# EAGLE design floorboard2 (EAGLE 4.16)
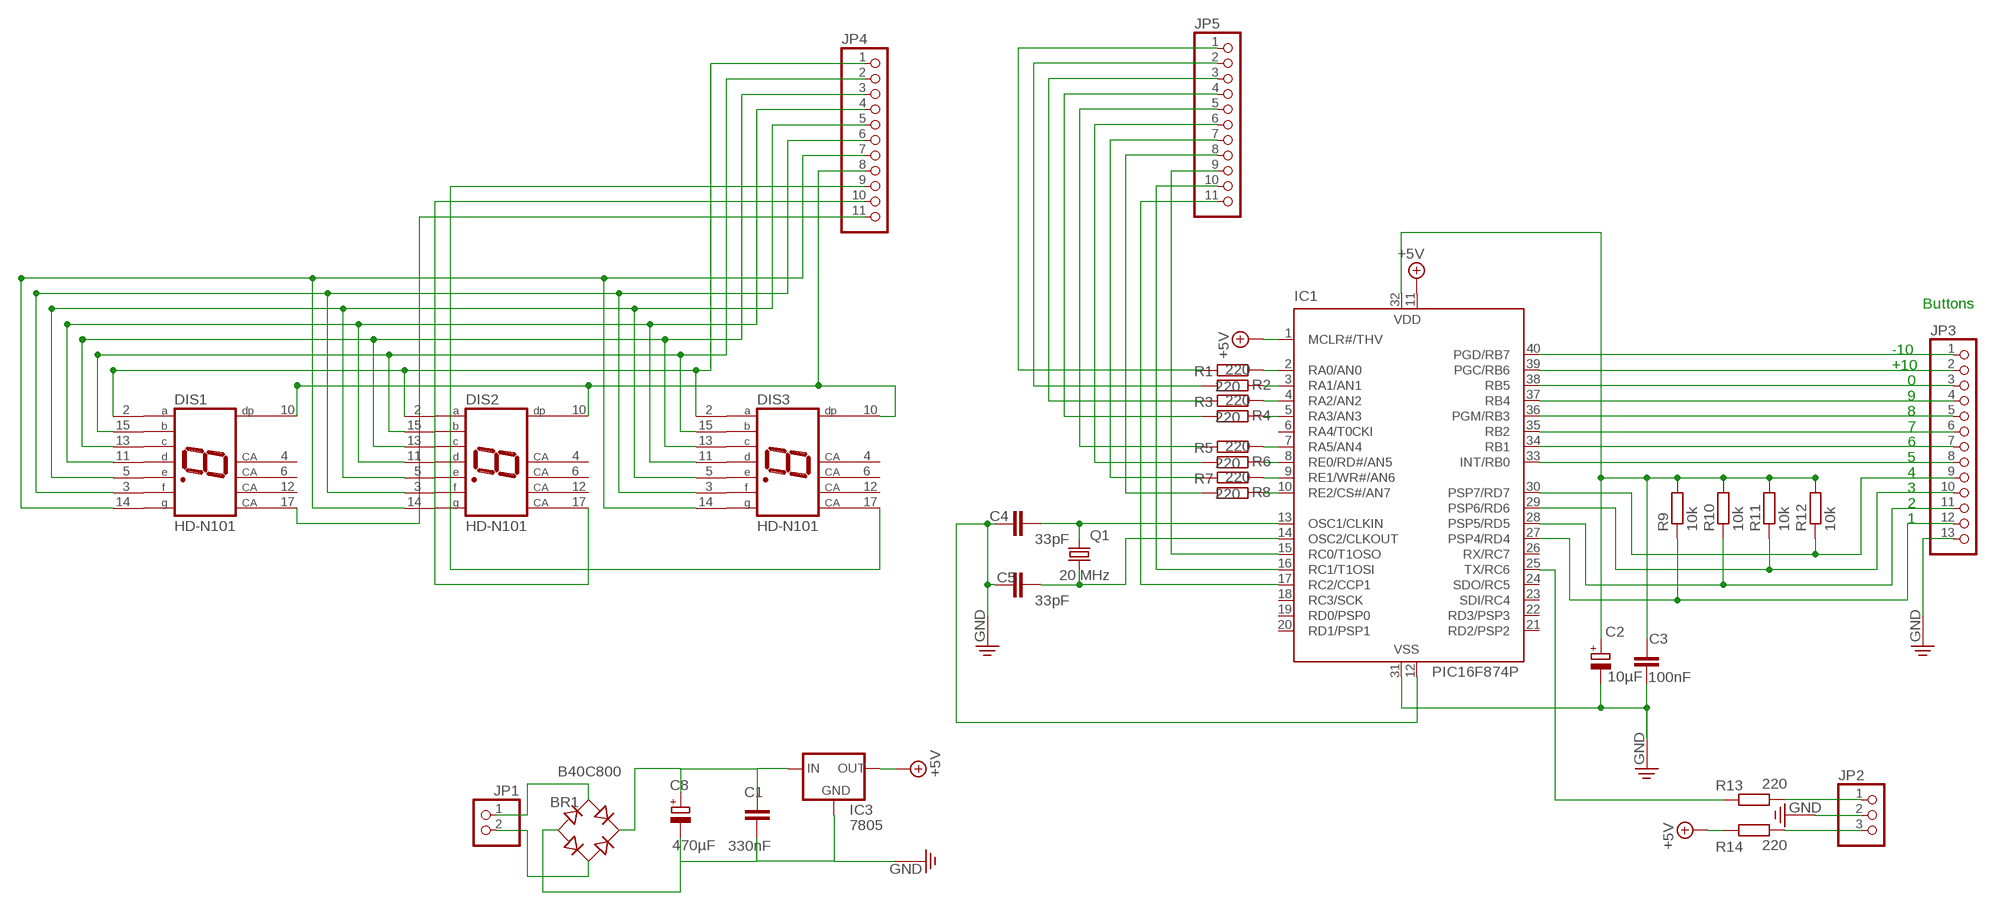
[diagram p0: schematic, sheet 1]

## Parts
BR1  B40C800  RB1A  [RB1A]
C1  330nF  C-EU025-025X050  [C025-025X050]
C2  10µF  CPOL-EUE2-5  [E2-5]
C3  100nF  C-EU025-025X050  [C025-025X050]
C4  33pF  C-EU025-025X050  [C025-025X050]
C5  33pF  C-EU025-025X050  [C025-025X050]
C8  470µF  CPOL-EUE2-5  [E2-5]
DIS1  HD-N101  [HDSP-Q]
DIS2  HD-N101  [HDSP-Q]
DIS3  HD-N101  [HDSP-Q]
IC1  PIC16F874P  [DIL40]
IC3  7805  78XXS  [78XXS]
JP1  PINHD-1X2  [1X02]
JP2  PINHD-1X3  [1X03]
JP3  PINHD-1X13  [1X13]
JP4  PINHD-1X11  [1X11]
JP5  PINHD-1X11  [1X11]
Q1  20 MHz  CRYTALHC18U-V  [HC18U-V]
R1  220  R-EU_0207/10  [0207/10]
R2  220  R-EU_0207/10  [0207/10]
R3  220  R-EU_0207/10  [0207/10]
R4  220  R-EU_0207/2V  [0207/2V]
R5  220  R-EU_0207/2V  [0207/2V]
R6  220  R-EU_0207/2V  [0207/2V]
R7  220  R-EU_0207/2V  [0207/2V]
R8  220  R-EU_0207/2V  [0207/2V]
R9  10k  R-EU_0207/10  [0207/10]
R10  10k  R-EU_0207/10  [0207/10]
R11  10k  R-EU_0207/10  [0207/10]
R12  10k  R-EU_0207/10  [0207/10]
R13  220  R-EU_0207/2V  [0207/2V]
R14  220  R-EU_0207/2V  [0207/2V]

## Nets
+5V: IC1.1(MCLR#/THV) IC1.11(VDD) IC3.OUT R14.1
+-9V: BR1.+ C1.1 C8.+ IC3.IN
GND: BR1.- C1.2 C2.- C3.2 C4.1 C5.1 C8.- IC1.12(VSS) IC1.31(VSS) IC3.GND JP2.2 JP3.13
N$1: BR1.AC1 JP1.1
N$2: BR1.AC2 JP1.2
N$4: IC1.2(RA0/AN0) R1.2
N$5: IC1.3(RA1/AN1) R2.1
N$6: IC1.4(RA2/AN2) R3.2
N$7: IC1.5(RA3/AN3) R4.1
N$8: IC1.7(RA5/AN4) R5.2
N$9: IC1.8(RE0/RD#/AN5) R6.1
N$10: IC1.9(RE1/WR#/AN6) R7.2
N$11: IC1.10(RE2/CS#/AN7) R8.1
N$12: IC1.40(PGD/RB7) JP3.1
N$13: IC1.39(PGC/RB6) JP3.2
N$14: IC1.38(RB5) JP3.3
N$15: IC1.37(RB4) JP3.4
N$16: IC1.36(PGM/RB3) JP3.5
N$17: IC1.35(RB2) JP3.6
N$18: IC1.34(RB1) JP3.7
N$19: IC1.33(INT/RB0) JP3.8
N$20: C2.+ C3.1 IC1.32(VDD) R9.2 R10.2 R11.2 R12.2
N$21: IC1.30(PSP7/RD7) JP3.9 R12.1
N$22: IC1.29(PSP6/RD6) JP3.10 R11.1
N$23: IC1.28(PSP5/RD5) JP3.11 R10.1
N$24: IC1.27(PSP4/RD4) JP3.12 R9.1
N$25: IC1.25(TX/RC6) R13.1
N$26: JP2.1 R13.2
N$27: JP2.3 R14.2
N$28: C4.2 IC1.13(OSC1/CLKIN) Q1.2
N$29: C5.2 IC1.14(OSC2/CLKOUT) Q1.1
N$30: DIS1.2(A) DIS2.2(A) DIS3.2(A) JP4.1
N$31: DIS1.15(B) DIS2.15(B) DIS3.15(B) JP4.2
N$32: DIS2.17(CA) JP4.10
N$33: DIS1.17(CA) JP4.11
N$37: JP5.7 R7.1
N$38: DIS1.13(C) DIS2.13(C) DIS3.13(C) JP4.3
N$39: DIS1.11(D) DIS2.11(D) DIS3.11(D) JP4.4
N$40: JP5.6 R6.2
N$41: DIS1.3(F) DIS2.3(F) DIS3.3(F) JP4.6
N$42: JP5.5 R5.1
N$43: JP5.4 R4.2
N$44: JP5.3 R3.1
N$45: JP5.2 R2.2
N$46: DIS1.5(E) DIS2.5(E) DIS3.5(E) JP4.5
N$47: JP5.1 R1.1
N$48: DIS1.14(G) DIS2.14(G) DIS3.14(G) JP4.7
N$49: JP5.8 R8.2
N$50: IC1.15(RC0/T1OSO) JP5.9
N$51: DIS1.10(DP) DIS2.10(DP) DIS3.10(DP) JP4.8
N$52: DIS3.17(CA) JP4.9
N$53: IC1.16(RC1/T1OSI) JP5.10
N$54: IC1.17(RC2/CCP1) JP5.11
Unconnected: DIS1.4(CA) DIS1.6(CA) DIS1.12(CA) DIS2.4(CA) DIS2.6(CA) DIS2.12(CA) DIS3.4(CA) DIS3.6(CA) DIS3.12(CA) IC1.6(RA4/T0CKI) IC1.18(RC3/SCK) IC1.19(RD0/PSP0) IC1.20(RD1/PSP1) IC1.21(RD2/PSP2) IC1.22(RD3/PSP3) IC1.23(SDI/RC4) IC1.24(SDO/RC5) IC1.26(RX/RC7)

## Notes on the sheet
- Buttons
- -10
- +10
- 0
- 9
- 8
- 7
- 6
- 5
- 4
- 3
- 2
- 1

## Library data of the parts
BR1 = rectifier:RB1A: RECTIFIER 1 A
C1 C3-C5 = rcl:C-EU: CAPACITOR, European symbol
C2 C8 = rcl:CPOL-EU: POLARIZED CAPACITOR, European symbol
DIS1-DIS3 = display-hp:HD-N101: LED DISPLAY 1-character 7 segment, decimal point right
IC1 = microchip:PIC16F87*: MICROCONTROLLER
IC3 = v-reg:78XXS: VOLTAGE REGULATOR
JP1 = pinhead:PINHD-1X2: PIN HEADER
JP2 = pinhead:PINHD-1X3: PIN HEADER
JP3 = pinhead:PINHD-1X13: PIN HEADER
JP4 JP5 = pinhead:PINHD-1X11: PIN HEADER
Q1 = crystal:CRYTAL: CRYSTAL
R1-R14 = rcl:R-EU_: RESISTOR, European symbol

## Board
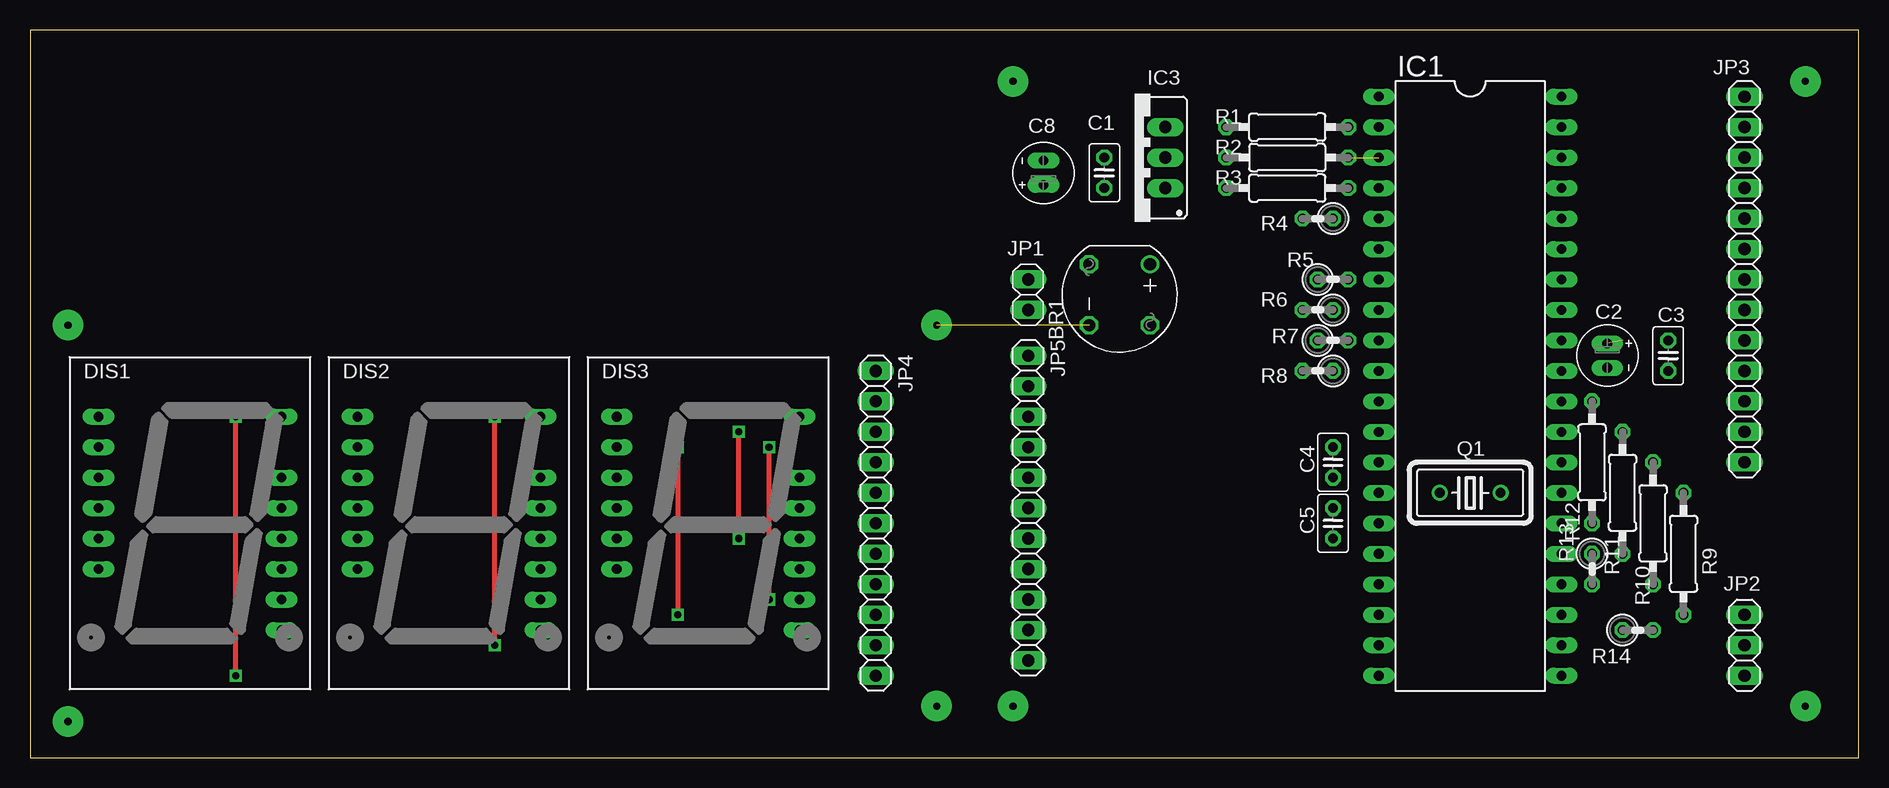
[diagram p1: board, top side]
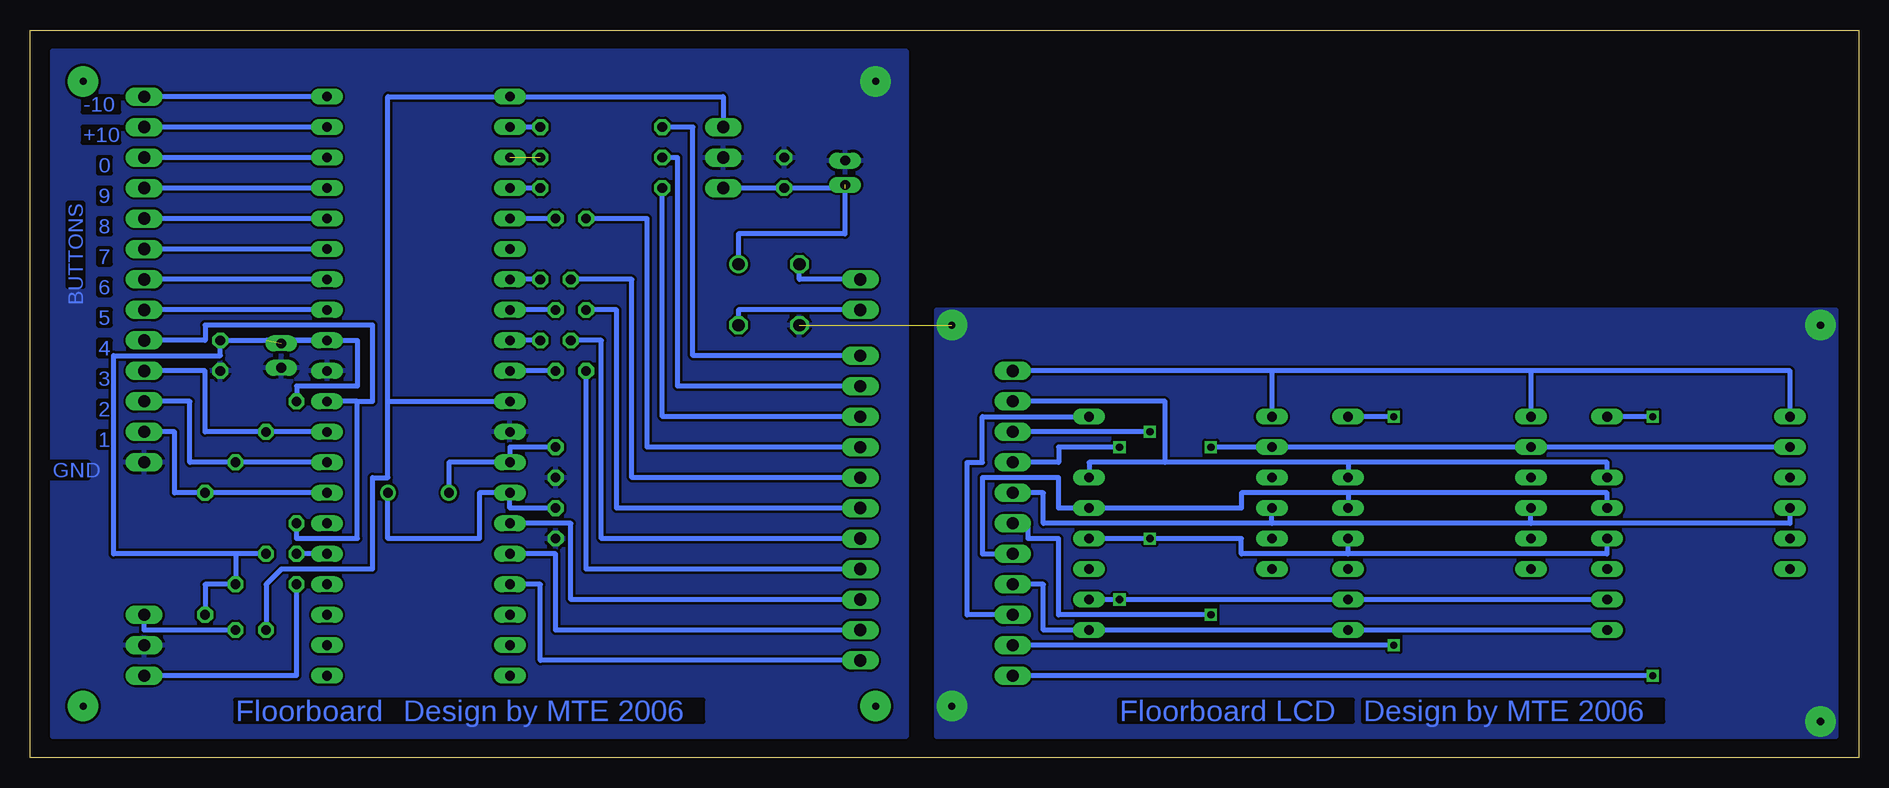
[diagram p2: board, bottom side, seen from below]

Size 152.38 x 60.63 mm. Coordinates in mm from the lower left corner, seen from the top.
Outline: 0,0 152.38,0 152.38,60.63 0,60.63 0,0
Copper layers (1*16): Top 0.035mm / dielectric 1.5mm / Bottom 0.035mm
Design rules "default": minimum track width 10mil, minimum drill 24mil, track to track 8mil, track to pad 8mil, pad to pad 8mil, via to via 8mil, smd to smd 8mil, copper to edge 40mil, drill to drill 8mil, minimum pad ring 10mil, minimum via ring 8mil, stop-mask expansion 4mil, vias tented up to drill 0mil, thermal gap 10mil

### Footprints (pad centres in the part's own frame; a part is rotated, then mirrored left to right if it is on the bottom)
RB1A = drill 1.016 round: + -2.54,2.54 | drill 1.016 octagon: - 2.54,-2.54; AC1 2.54,2.54; AC2 -2.54,-2.54
C025-025X050 = drill 0.813 octagon: 1 -1.27,0; 2 1.27,0
E2-5 = drill 0.813 pad 1.27 long: + -1.016,0; - 1.016,0
HDSP-Q = drill 0.813 long: 2 -7.62,8.89; 3 -7.62,6.35; 4 -7.62,3.81; 5 -7.62,1.27; 6 -7.62,-1.27; 7 -7.62,-3.81; 10 7.62,-8.89; 11 7.62,-6.35; 12 7.62,-3.81; 13 7.62,-1.27; 14 7.62,1.27; 15 7.62,3.81; 17 7.62,8.89
DIL40 = drill 0.813 long: 1 -24.13,-7.62; 2 -21.59,-7.62; 3 -19.05,-7.62; 4 -16.51,-7.62; 5 -13.97,-7.62; 6 -11.43,-7.62; 7 -8.89,-7.62; 8 -6.35,-7.62; 9 -3.81,-7.62; 10 -1.27,-7.62; 11 1.27,-7.62; 12 3.81,-7.62; 13 6.35,-7.62; 14 8.89,-7.62; 15 11.43,-7.62; 16 13.97,-7.62; 17 16.51,-7.62; 18 19.05,-7.62; 19 21.59,-7.62; 20 24.13,-7.62; 21 24.13,7.62; 22 21.59,7.62; 23 19.05,7.62; 24 16.51,7.62; 25 13.97,7.62; 26 11.43,7.62; 27 8.89,7.62; 28 6.35,7.62; 29 3.81,7.62; 30 1.27,7.62; 31 -1.27,7.62; 32 -3.81,7.62; 33 -6.35,7.62; 34 -8.89,7.62; 35 -11.43,7.62; 36 -13.97,7.62; 37 -16.51,7.62; 38 -19.05,7.62; 39 -21.59,7.62; 40 -24.13,7.62
78XXS = drill 1.016 long: GND 0,-2.54; IN -2.54,-2.54; OUT 2.54,-2.54
1X02 = drill 1.016 long: 1 -1.27,0; 2 1.27,0
1X03 = drill 1.016 long: 1 -2.54,0; 2 0,0; 3 2.54,0
1X13 = drill 1.016 long: 1 -15.24,0; 2 -12.7,0; 3 -10.16,0; 4 -7.62,0; 5 -5.08,0; 6 -2.54,0; 7 0,0; 8 2.54,0; 9 5.08,0; 10 7.62,0; 11 10.16,0; 12 12.7,0; 13 15.24,0
1X11 = drill 1.016 long: 1 -12.7,0; 2 -10.16,0; 3 -7.62,0; 4 -5.08,0; 5 -2.54,0; 6 0,0; 7 2.54,0; 8 5.08,0; 9 7.62,0; 10 10.16,0; 11 12.7,0
HC18U-V = drill 0.813 round: 1 -2.54,0; 2 2.54,0
0207/10 = drill 0.813 octagon: 1 -5.08,0; 2 5.08,0
0207/2V = drill 0.813 octagon: 1 -1.27,0; 2 1.27,0

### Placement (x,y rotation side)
BR1  90.8,38.57 270 top
C1  89.53,48.73 90 top
C2  131.44,33.49 270 top
C3  136.52,33.49 270 top
C4  108.58,24.6 90 top
C5  108.58,19.52 90 top
C8  84.45,48.73 90 top
DIS1  13.33,19.52 0 top
DIS2  34.92,19.52 0 top
DIS3  56.51,19.52 0 top
IC1  120.01,30.95 270 top
IC3  92.07,50 90 top
JP1  83.18,38.57 90 top
JP2  142.87,9.36 90 top
JP3  142.87,39.84 270 top
JP4  70.48,19.52 270 top
JP5  83.18,20.79 270 top
Q1  120.01,22.06 180 top
R1  104.77,52.54 0 top
R2  104.77,50 180 top
R3  104.77,47.46 0 top
R4  107.31,44.92 180 top
R5  108.58,39.84 0 top
R6  107.31,37.3 180 top
R7  108.58,34.76 0 top
R8  107.31,32.22 180 top
R9  137.79,16.98 270 top
R10  135.25,19.52 270 top
R11  132.71,22.06 270 top
R12  130.17,24.6 90 top
R13  130.17,15.71 270 top
R14  133.98,10.63 0 top

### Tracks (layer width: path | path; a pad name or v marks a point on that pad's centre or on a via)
+5V
  Bottom 0.406: IC3.OUT 94.61,55.08 IC1.1 122.55,55.08 122.55,29.68 | 122.55,29.68 IC1.11 | R14.1 132.71,14.44 131.44,15.71 123.82,15.71 123.82,23.33 122.55,23.33 122.55,29.68
+-9V  (1 unrouted)
  Bottom 0.406: 84.45,47.46 C1.1 | BR1.+ 93.34,43.65 84.45,43.65 84.45,47.46 | 84.45,47.46 IC3.IN
GND  (via drill 0.6 pad 2.54)  (1 unrouted)
  other vias: 81.91,56.35 75.56,36.03 75.56,4.28 3.17,3.01 3.17,36.03
  pour Bottom: 150.49,58.89 79.37,58.89 79.37,1.74 150.49,1.74
  pour Bottom: 1.9,37.3 1.9,1.74 76.83,1.74 76.83,37.3
N$1
  Bottom 0.406: BR1.AC1 93.34,37.3 JP1.1
N$2
  Bottom 0.406: JP1.2 88.26,39.84 BR1.AC2
N$3  (via drill 0.6 pad 2.54)
  other vias: 147.95,56.35
N$4
  Bottom 0.406: R1.2 IC1.2
N$5  (1 unrouted)
N$6
  Bottom 0.406: R3.2 IC1.4
N$7
  Bottom 0.406: R4.1 IC1.5
N$8
  Bottom 0.406: R5.2 IC1.7
N$9
  Bottom 0.406: R6.1 IC1.8
N$10
  Bottom 0.406: R7.2 IC1.9
N$11
  Bottom 0.406: R8.1 IC1.10
N$12
  Bottom 0.406: IC1.40 JP3.1
N$13
  Bottom 0.406: IC1.39 JP3.2
N$14
  Bottom 0.406: IC1.38 JP3.3
N$15
  Bottom 0.406: IC1.37 JP3.4
N$16
  Bottom 0.406: IC1.36 JP3.5
N$17
  Bottom 0.406: IC1.35 JP3.6
N$18
  Bottom 0.406: IC1.34 JP3.7
N$19
  Bottom 0.406: IC1.33 JP3.8
N$20  (1 unrouted)
  Bottom 0.406: IC1.32 132.71,34.76 IC1.32 | IC1.32 C3.1 136.52,33.49 145.41,33.49 145.41,16.98 135.25,16.98 | R12.2 130.17,30.95 125.09,30.95 125.09,34.76 IC1.32 | R11.2 135.25,16.98 | 135.25,16.98 R10.2 137.79,14.44 R9.2
N$21
  Bottom 0.406: 125.09,29.68 IC1.30 | 125.09,29.68 125.09,18.25 130.17,18.25 R12.1 | 125.09,29.68 123.82,29.68 123.82,36.03 137.79,36.03 137.79,34.76 JP3.9
N$22
  Bottom 0.406: IC1.29 R11.1 137.79,27.14 137.79,32.22 JP3.10
N$23
  Bottom 0.406: IC1.28 R10.1 139.06,24.6 139.06,29.68 JP3.11
N$24
  Bottom 0.406: IC1.27 R9.1 140.33,22.06 140.33,27.14 JP3.12
N$25
  Bottom 0.406: IC1.25 R13.1
N$26
  Bottom 0.406: R13.2 130.17,6.82 JP2.1
N$27
  Bottom 0.406: R14.2 142.87,10.63 JP2.3
N$28
  Bottom 0.406: C4.2 112.39,25.87 IC1.13 117.47,24.6 Q1.2
N$29
  Bottom 0.406: C5.2 112.39,20.79 IC1.14 114.93,22.06 114.93,18.25 122.55,18.25 Q1.1
N$30
  Bottom 0.406: DIS1.2 5.71,32.22 27.3,32.22 | 27.3,32.22 DIS2.2 | 27.3,32.22 48.89,32.22 | 48.89,32.22 DIS3.2 | 48.89,32.22 JP4.1
N$31
  Bottom 0.406: DIS1.15 20.95,24.6 42.54,24.6 | 42.54,24.6 DIS2.15 | 42.54,24.6 57.78,24.6 | 57.78,24.6 64.13,24.6 DIS3.15 | JP4.2 57.78,29.68 57.78,24.6
N$32  (via drill 0.6)
  Top 0.406: v38.73,9.36 v38.73,28.41
  Bottom 0.406: v38.73,9.36 JP4.10 | v38.73,28.41 DIS2.17
N$33  (via drill 0.6)
  Top 0.406: v17.14,6.82 v17.14,28.41
  Bottom 0.406: v17.14,6.82 JP4.11 | v17.14,28.41 DIS1.17
N$34  (via drill 0.6 pad 2.54)
  other vias: 81.91,4.28
N$35  (via drill 0.6 pad 2.54)
  other vias: 147.95,4.28
N$37
  Bottom 0.406: JP5.7 104.77,18.25 104.77,34.76 R7.1
N$38  (via drill 0.6)
  Top 0.406: v59.05,18.25 v59.05,27.14
  Bottom 0.406: DIS3.13 v59.05,18.25 51.43,18.25 51.43,16.98 42.54,16.98 | 42.54,16.98 DIS2.13 | 42.54,16.98 20.95,16.98 DIS1.13 | v59.05,27.14 JP4.3
N$39  (via drill 0.6)
  Top 0.406: v61.59,13.17 v61.59,25.87
  Bottom 0.406: DIS3.11 v61.59,13.17 DIS2.11 DIS1.11 | JP4.4 66.67,24.6 66.67,25.87 v61.59,25.87
N$40
  Bottom 0.406: R6.2 103.5,37.3 103.5,20.79 JP5.6
N$41  (via drill 0.6)
  Top 0.406: v53.97,25.87 v53.97,11.9
  Bottom 0.406: DIS1.3 DIS2.3 DIS3.3 v53.97,25.87 | JP4.6 69.21,19.52 69.21,18.25 66.67,18.25 66.67,11.9 v53.97,11.9
N$42
  Bottom 0.406: JP5.5 102.23,23.33 102.23,39.84 R5.1
N$43
  Bottom 0.406: R4.2 100.96,44.92 100.96,25.87 JP5.4
N$44
  Bottom 0.406: R3.1 99.69,28.41 JP5.3
N$45
  Bottom 0.406: JP5.2 98.42,30.95 98.42,50 R2.2
N$46
  Bottom 0.406: 48.89,19.52 DIS3.5 | DIS1.5 5.71,19.52 27.3,19.52 | 27.3,19.52 48.89,19.52 | 27.3,19.52 DIS2.5 | 48.89,19.52 67.94,19.52 67.94,22.06 JP4.5
N$47
  Bottom 0.406: R1.1 97.15,52.54 97.15,33.49 JP5.1
N$48
  Bottom 0.406: DIS1.14 20.95,22.06 42.54,22.06 | 42.54,22.06 DIS2.14 | 42.54,22.06 51.43,22.06 51.43,20.79 DIS3.14 66.67,20.79 66.67,23.33 73.02,23.33 73.02,16.98 JP4.7
N$49
  Bottom 0.406: R8.2 106.04,15.71 JP5.8
N$50
  Bottom 0.406: JP5.9 107.31,13.17 107.31,19.52 IC1.15
N$51
  Bottom 0.406: DIS1.10 DIS2.10 DIS3.10 67.94,10.63 67.94,14.44 JP4.8
N$52
  Bottom 0.406: JP4.9 74.29,11.9 74.29,24.6 73.02,24.6 73.02,28.41 DIS3.17
N$53
  Bottom 0.406: JP5.10 108.58,10.63 108.58,16.98 IC1.16
N$54
  Bottom 0.406: JP5.11 109.85,8.09 109.85,14.44 IC1.17

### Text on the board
Bottom: -10 | +10 | 0 | 9 | BUTTONS | 8 | 7 | 6 | 5 | 4 | 3 | 2 | 1 | GND | Design by MTE 2006 | Floorboard LCD | Design by MTE 2006 | Floorboard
